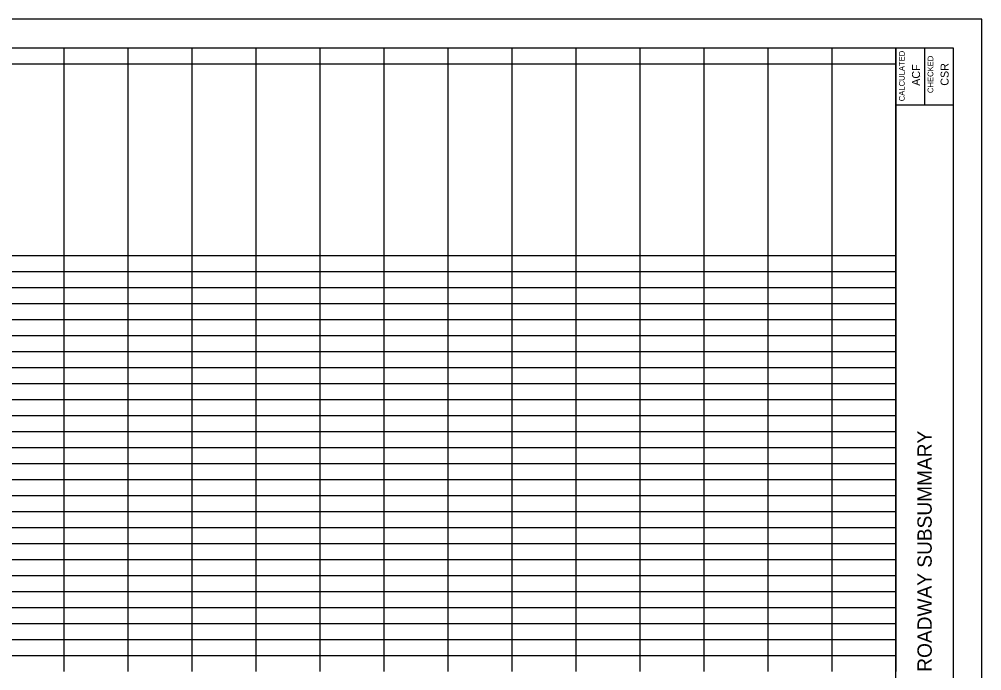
# Model space of a CAD drawing. Extents: x 0 to 34, y 0 to 22.
# Drawn here: x 17.17 to 34, y 10.6 to 22 of the extents above; entities that cross this region are included whole.
import ezdxf

# ---------------------------------------------------------------- set-up
doc = ezdxf.new("R2010")
doc.units = 0
for name, color, linetype in [('SH_Border', 7, 'Continuous'), ('SH_Cut_Line', 7, 'Continuous'), ('SH_Data', 7, 'Continuous')]:
    doc.layers.add(name, color=color, linetype=linetype)

msp = doc.modelspace()

# ---------------------------------------------------------------- linework, layer by layer
at = {"layer": 'SH_Border'}
for p, q in [((32.5, 0.5), (32.5, 21.5)), ((33, 21.5), (33, 20.5)), ((32.5, 20.5), (33.5, 20.5))]:
    msp.add_line(p, q, dxfattribs=at)
msp.add_lwpolyline([(2, 21.5), (33.5, 21.5), (33.5, 0.5), (2, 0.5)], close=True, dxfattribs=at)
at = {"layer": 'SH_Cut_Line'}
msp.add_lwpolyline([(0, 0), (34, 0), (34, 22), (0, 22)], close=True, dxfattribs=at)
at = {"layer": 'SH_Data'}
for p, q in [((15.706, 21.5), (17.945, 21.5)), ((17.945, 21.5), (21.304, 21.5)), ((17.945, 21.5), (17.945, 20.381)), ((19.065, 21.5), (19.065, 20.381)), ((20.184, 21.5), (20.184, 20.381)), ((21.304, 21.5), (22.423, 21.5)), ((21.304, 21.5), (21.304, 20.381)), ((22.423, 21.5), (28.022, 21.5)), ((22.423, 21.5), (22.423, 20.381)), ((23.543, 21.5), (23.543, 20.381)), ((24.663, 21.5), (24.663, 20.381)), ((25.782, 21.5), (25.782, 20.381)), ((26.902, 21.5), (26.902, 20.381)), ((28.022, 21.5), (32.5, 21.5)), ((28.022, 21.5), (28.022, 20.381)), ((29.141, 21.5), (29.141, 20.381)), ((30.261, 21.5), (30.261, 20.381)), ((31.38, 21.5), (31.38, 20.381)), ((32.5, 21.5), (32.5, 20.381)), ((15.706, 21.22), (17.945, 21.22)), ((17.945, 21.22), (21.304, 21.22)), ((21.304, 21.22), (22.423, 21.22)), ((22.423, 21.22), (28.022, 21.22)), ((28.022, 21.22), (32.5, 21.22)), ((32.92, 21.004), (32.92, 21.004)), ((33.42, 21.004), (33.42, 21.004)), ((17.945, 20.381), (17.945, 18.983)), ((19.065, 20.381), (19.065, 18.983)), ((20.184, 20.381), (20.184, 18.983)), ((21.304, 20.381), (21.304, 18.983)), ((22.423, 20.381), (22.423, 18.983)), ((23.543, 20.381), (23.543, 18.983)), ((24.663, 20.381), (24.663, 18.983)), ((25.782, 20.381), (25.782, 18.983)), ((26.902, 20.381), (26.902, 18.983)), ((28.022, 20.381), (28.022, 18.983)), ((29.141, 20.381), (29.141, 18.983)), ((30.261, 20.381), (30.261, 18.983)), ((31.38, 20.381), (31.38, 18.983)), ((32.5, 20.381), (32.5, 18.983)), ((17.945, 18.983), (17.945, 18.143)), ((19.065, 18.983), (19.065, 18.143)), ((20.184, 18.983), (20.184, 18.143)), ((21.304, 18.983), (21.304, 18.143)), ((22.423, 18.983), (22.423, 18.143)), ((23.543, 18.983), (23.543, 18.143)), ((24.663, 18.983), (24.663, 18.143)), ((25.782, 18.983), (25.782, 18.143)), ((26.902, 18.983), (26.902, 18.143)), ((28.022, 18.983), (28.022, 18.143)), ((29.141, 18.983), (29.141, 18.143)), ((30.261, 18.983), (30.261, 18.143)), ((31.38, 18.983), (31.38, 18.143)), ((32.5, 18.983), (32.5, 18.143)), ((17.945, 18.143), (17.945, 17.864)), ((19.065, 18.143), (19.065, 17.864)), ((20.184, 18.143), (20.184, 17.864)), ((21.304, 18.143), (21.304, 17.864)), ((22.423, 18.143), (22.423, 17.864)), ((23.543, 18.143), (23.543, 17.864)), ((24.663, 18.143), (24.663, 17.864)), ((25.782, 18.143), (25.782, 17.864)), ((26.902, 18.143), (26.902, 17.864)), ((28.022, 18.143), (28.022, 17.864)), ((29.141, 18.143), (29.141, 17.864)), ((30.261, 18.143), (30.261, 17.864)), ((31.38, 18.143), (31.38, 17.864)), ((32.5, 18.143), (32.5, 17.864)), ((15.706, 17.864), (17.945, 17.864)), ((17.945, 17.864), (21.304, 17.864)), ((17.945, 17.864), (17.945, 17.584)), ((19.065, 17.864), (19.065, 17.584)), ((20.184, 17.864), (20.184, 17.584)), ((21.304, 17.864), (22.423, 17.864)), ((21.304, 17.864), (21.304, 17.584)), ((22.423, 17.864), (28.022, 17.864)), ((22.423, 17.864), (22.423, 17.584)), ((23.543, 17.864), (23.543, 17.584)), ((24.663, 17.864), (24.663, 17.584)), ((25.782, 17.864), (25.782, 17.584)), ((26.902, 17.864), (26.902, 17.584)), ((28.022, 17.864), (32.5, 17.864)), ((28.022, 17.864), (28.022, 17.584)), ((29.141, 17.864), (29.141, 17.584)), ((30.261, 17.864), (30.261, 17.584)), ((31.38, 17.864), (31.38, 17.584)), ((32.5, 17.864), (32.5, 17.584)), ((15.706, 17.584), (17.945, 17.584)), ((17.945, 17.584), (21.304, 17.584)), ((17.945, 17.584), (17.945, 17.304)), ((19.065, 17.584), (19.065, 17.304)), ((20.184, 17.584), (20.184, 17.304)), ((21.304, 17.584), (22.423, 17.584)), ((21.304, 17.584), (21.304, 17.304)), ((22.423, 17.584), (28.022, 17.584)), ((22.423, 17.584), (22.423, 17.304)), ((23.543, 17.584), (23.543, 17.304)), ((24.663, 17.584), (24.663, 17.304)), ((25.782, 17.584), (25.782, 17.304)), ((26.902, 17.584), (26.902, 17.304)), ((28.022, 17.584), (32.5, 17.584)), ((28.022, 17.584), (28.022, 17.304)), ((29.141, 17.584), (29.141, 17.304)), ((30.261, 17.584), (30.261, 17.304)), ((31.38, 17.584), (31.38, 17.304)), ((32.5, 17.584), (32.5, 17.304)), ((15.706, 17.304), (17.945, 17.304)), ((17.945, 17.304), (21.304, 17.304)), ((17.945, 17.304), (17.945, 17.025)), ((19.065, 17.304), (19.065, 17.025)), ((20.184, 17.304), (20.184, 17.025)), ((21.304, 17.304), (22.423, 17.304)), ((21.304, 17.304), (21.304, 17.025)), ((22.423, 17.304), (28.022, 17.304)), ((22.423, 17.304), (22.423, 17.025)), ((23.543, 17.304), (23.543, 17.025)), ((24.663, 17.304), (24.663, 17.025)), ((25.782, 17.304), (25.782, 17.025)), ((26.902, 17.304), (26.902, 17.025)), ((28.022, 17.304), (32.5, 17.304)), ((28.022, 17.304), (28.022, 17.025)), ((29.141, 17.304), (29.141, 17.025)), ((30.261, 17.304), (30.261, 17.025)), ((31.38, 17.304), (31.38, 17.025)), ((32.5, 17.304), (32.5, 17.025)), ((15.706, 17.025), (17.945, 17.025)), ((17.945, 17.025), (21.304, 17.025)), ((17.945, 17.025), (17.945, 16.745)), ((19.065, 17.025), (19.065, 16.745)), ((20.184, 17.025), (20.184, 16.745)), ((21.304, 17.025), (22.423, 17.025)), ((21.304, 17.025), (21.304, 16.745)), ((22.423, 17.025), (28.022, 17.025)), ((22.423, 17.025), (22.423, 16.745)), ((23.543, 17.025), (23.543, 16.745)), ((24.663, 17.025), (24.663, 16.745)), ((25.782, 17.025), (25.782, 16.745)), ((26.902, 17.025), (26.902, 16.745)), ((28.022, 17.025), (32.5, 17.025)), ((28.022, 17.025), (28.022, 16.745)), ((29.141, 17.025), (29.141, 16.745)), ((30.261, 17.025), (30.261, 16.745)), ((31.38, 17.025), (31.38, 16.745)), ((32.5, 17.025), (32.5, 16.745)), ((15.706, 16.745), (17.945, 16.745)), ((17.945, 16.745), (21.304, 16.745)), ((17.945, 16.745), (17.945, 16.465)), ((19.065, 16.745), (19.065, 16.465)), ((20.184, 16.745), (20.184, 16.465)), ((21.304, 16.745), (22.423, 16.745)), ((21.304, 16.745), (21.304, 16.465)), ((22.423, 16.745), (28.022, 16.745)), ((22.423, 16.745), (22.423, 16.465)), ((23.543, 16.745), (23.543, 16.465)), ((24.663, 16.745), (24.663, 16.465)), ((25.782, 16.745), (25.782, 16.465)), ((26.902, 16.745), (26.902, 16.465)), ((28.022, 16.745), (32.5, 16.745)), ((28.022, 16.745), (28.022, 16.465)), ((29.141, 16.745), (29.141, 16.465)), ((30.261, 16.745), (30.261, 16.465)), ((31.38, 16.745), (31.38, 16.465)), ((32.5, 16.745), (32.5, 16.465)), ((15.706, 16.465), (17.945, 16.465)), ((17.945, 16.465), (21.304, 16.465)), ((17.945, 16.465), (17.945, 16.185)), ((19.065, 16.465), (19.065, 16.185)), ((20.184, 16.465), (20.184, 16.185)), ((21.304, 16.465), (22.423, 16.465)), ((21.304, 16.465), (21.304, 16.185)), ((22.423, 16.465), (28.022, 16.465)), ((22.423, 16.465), (22.423, 16.185)), ((23.543, 16.465), (23.543, 16.185)), ((24.663, 16.465), (24.663, 16.185)), ((25.782, 16.465), (25.782, 16.185)), ((26.902, 16.465), (26.902, 16.185)), ((28.022, 16.465), (32.5, 16.465)), ((28.022, 16.465), (28.022, 16.185)), ((29.141, 16.465), (29.141, 16.185)), ((30.261, 16.465), (30.261, 16.185)), ((31.38, 16.465), (31.38, 16.185)), ((32.5, 16.465), (32.5, 16.185)), ((15.706, 16.185), (17.945, 16.185)), ((17.945, 16.185), (21.304, 16.185)), ((17.945, 16.185), (17.945, 15.906)), ((19.065, 16.185), (19.065, 15.906)), ((20.184, 16.185), (20.184, 15.906)), ((21.304, 16.185), (22.423, 16.185)), ((21.304, 16.185), (21.304, 15.906)), ((22.423, 16.185), (28.022, 16.185)), ((22.423, 16.185), (22.423, 15.906)), ((23.543, 16.185), (23.543, 15.906)), ((24.663, 16.185), (24.663, 15.906)), ((25.782, 16.185), (25.782, 15.906)), ((26.902, 16.185), (26.902, 15.906)), ((28.022, 16.185), (32.5, 16.185)), ((28.022, 16.185), (28.022, 15.906)), ((29.141, 16.185), (29.141, 15.906)), ((30.261, 16.185), (30.261, 15.906)), ((31.38, 16.185), (31.38, 15.906)), ((32.5, 16.185), (32.5, 15.906)), ((15.706, 15.906), (17.945, 15.906)), ((17.945, 15.906), (21.304, 15.906)), ((17.945, 15.906), (17.945, 15.626)), ((19.065, 15.906), (19.065, 15.626)), ((20.184, 15.906), (20.184, 15.626)), ((21.304, 15.906), (22.423, 15.906)), ((21.304, 15.906), (21.304, 15.626)), ((22.423, 15.906), (28.022, 15.906)), ((22.423, 15.906), (22.423, 15.626)), ((23.543, 15.906), (23.543, 15.626)), ((24.663, 15.906), (24.663, 15.626)), ((25.782, 15.906), (25.782, 15.626)), ((26.902, 15.906), (26.902, 15.626)), ((28.022, 15.906), (32.5, 15.906)), ((28.022, 15.906), (28.022, 15.626)), ((29.141, 15.906), (29.141, 15.626)), ((30.261, 15.906), (30.261, 15.626)), ((31.38, 15.906), (31.38, 15.626)), ((32.5, 15.906), (32.5, 15.626)), ((15.706, 15.626), (17.945, 15.626)), ((17.945, 15.626), (21.304, 15.626)), ((17.945, 15.626), (17.945, 15.066)), ((19.065, 15.626), (19.065, 15.066)), ((20.184, 15.626), (20.184, 15.066)), ((21.304, 15.626), (22.423, 15.626)), ((21.304, 15.626), (21.304, 15.066)), ((22.423, 15.626), (28.022, 15.626)), ((22.423, 15.626), (22.423, 15.066)), ((23.543, 15.626), (23.543, 15.066)), ((24.663, 15.626), (24.663, 15.066)), ((25.782, 15.626), (25.782, 15.066)), ((26.902, 15.626), (26.902, 15.066)), ((28.022, 15.626), (32.5, 15.626)), ((28.022, 15.626), (28.022, 15.066)), ((29.141, 15.626), (29.141, 15.066)), ((30.261, 15.626), (30.261, 15.066)), ((31.38, 15.626), (31.38, 15.066)), ((32.5, 15.626), (32.5, 15.066)), ((15.706, 15.346), (17.945, 15.346)), ((17.945, 15.346), (21.304, 15.346)), ((21.304, 15.346), (22.423, 15.346)), ((22.423, 15.346), (28.022, 15.346)), ((28.022, 15.346), (32.5, 15.346)), ((15.706, 15.066), (17.945, 15.066)), ((17.945, 15.066), (21.304, 15.066)), ((17.945, 15.066), (17.945, 13.668)), ((19.065, 15.066), (19.065, 13.668)), ((20.184, 15.066), (20.184, 13.668)), ((21.304, 15.066), (22.423, 15.066)), ((21.304, 15.066), (21.304, 13.668)), ((22.423, 15.066), (28.022, 15.066)), ((22.423, 15.066), (22.423, 13.668)), ((23.543, 15.066), (23.543, 13.668)), ((24.663, 15.066), (24.663, 13.668)), ((25.782, 15.066), (25.782, 13.668)), ((26.902, 15.066), (26.902, 13.668)), ((28.022, 15.066), (32.5, 15.066)), ((28.022, 15.066), (28.022, 13.668)), ((29.141, 15.066), (29.141, 13.668)), ((30.261, 15.066), (30.261, 13.668)), ((31.38, 15.066), (31.38, 13.668)), ((32.5, 15.066), (32.5, 13.668)), ((15.706, 14.787), (17.945, 14.787)), ((17.945, 14.787), (21.304, 14.787)), ((21.304, 14.787), (22.423, 14.787)), ((22.423, 14.787), (28.022, 14.787)), ((28.022, 14.787), (32.5, 14.787)), ((15.706, 14.507), (17.945, 14.507)), ((17.945, 14.507), (21.304, 14.507)), ((21.304, 14.507), (22.423, 14.507)), ((22.423, 14.507), (28.022, 14.507)), ((28.022, 14.507), (32.5, 14.507)), ((15.706, 14.227), (17.945, 14.227)), ((17.945, 14.227), (21.304, 14.227)), ((21.304, 14.227), (22.423, 14.227)), ((22.423, 14.227), (28.022, 14.227)), ((28.022, 14.227), (32.5, 14.227)), ((15.706, 13.948), (17.945, 13.948)), ((17.945, 13.948), (21.304, 13.948)), ((21.304, 13.948), (22.423, 13.948)), ((22.423, 13.948), (28.022, 13.948)), ((28.022, 13.948), (32.5, 13.948)), ((15.706, 13.668), (17.945, 13.668)), ((17.945, 13.668), (21.304, 13.668)), ((17.945, 13.668), (17.945, 11.99)), ((19.065, 13.668), (19.065, 11.99)), ((20.184, 13.668), (20.184, 11.99)), ((21.304, 13.668), (22.423, 13.668)), ((21.304, 13.668), (21.304, 11.99)), ((22.423, 13.668), (28.022, 13.668)), ((22.423, 13.668), (22.423, 11.99)), ((23.543, 13.668), (23.543, 11.99)), ((24.663, 13.668), (24.663, 11.99)), ((25.782, 13.668), (25.782, 11.99)), ((26.902, 13.668), (26.902, 11.99)), ((28.022, 13.668), (32.5, 13.668)), ((28.022, 13.668), (28.022, 11.99)), ((29.141, 13.668), (29.141, 11.99)), ((30.261, 13.668), (30.261, 11.99)), ((31.38, 13.668), (31.38, 11.99)), ((32.5, 13.668), (32.5, 11.99)), ((15.706, 13.388), (17.945, 13.388)), ((17.945, 13.388), (21.304, 13.388)), ((21.304, 13.388), (22.423, 13.388)), ((22.423, 13.388), (28.022, 13.388)), ((28.022, 13.388), (32.5, 13.388)), ((33, 13.292), (33, 13.292)), ((15.706, 13.108), (17.945, 13.108)), ((17.945, 13.108), (21.304, 13.108)), ((21.304, 13.108), (22.423, 13.108)), ((22.423, 13.108), (28.022, 13.108)), ((28.022, 13.108), (32.5, 13.108)), ((15.706, 12.829), (17.945, 12.829)), ((17.945, 12.829), (21.304, 12.829)), ((21.304, 12.829), (22.423, 12.829)), ((22.423, 12.829), (28.022, 12.829)), ((28.022, 12.829), (32.5, 12.829)), ((15.706, 12.549), (17.945, 12.549)), ((17.945, 12.549), (21.304, 12.549)), ((21.304, 12.549), (22.423, 12.549)), ((22.423, 12.549), (28.022, 12.549)), ((28.022, 12.549), (32.5, 12.549)), ((15.706, 12.269), (17.945, 12.269)), ((17.945, 12.269), (21.304, 12.269)), ((21.304, 12.269), (22.423, 12.269)), ((22.423, 12.269), (28.022, 12.269)), ((28.022, 12.269), (32.5, 12.269)), ((15.706, 11.99), (17.945, 11.99)), ((17.945, 11.99), (21.304, 11.99)), ((17.945, 11.99), (17.945, 10.591)), ((19.065, 11.99), (19.065, 10.591)), ((20.184, 11.99), (20.184, 10.591)), ((21.304, 11.99), (22.423, 11.99)), ((21.304, 11.99), (21.304, 10.591)), ((22.423, 11.99), (28.022, 11.99)), ((22.423, 11.99), (22.423, 10.591)), ((23.543, 11.99), (23.543, 10.591)), ((24.663, 11.99), (24.663, 10.591)), ((25.782, 11.99), (25.782, 10.591)), ((26.902, 11.99), (26.902, 10.591)), ((28.022, 11.99), (32.5, 11.99)), ((28.022, 11.99), (28.022, 10.591)), ((29.141, 11.99), (29.141, 10.591)), ((30.261, 11.99), (30.261, 10.591)), ((31.38, 11.99), (31.38, 10.591)), ((32.5, 11.99), (32.5, 10.591)), ((15.706, 11.71), (17.945, 11.71)), ((17.945, 11.71), (21.304, 11.71)), ((21.304, 11.71), (22.423, 11.71)), ((22.423, 11.71), (28.022, 11.71)), ((28.022, 11.71), (32.5, 11.71)), ((15.706, 11.43), (17.945, 11.43)), ((17.945, 11.43), (21.304, 11.43)), ((21.304, 11.43), (22.423, 11.43)), ((22.423, 11.43), (28.022, 11.43)), ((28.022, 11.43), (32.5, 11.43)), ((15.706, 11.15), (17.945, 11.15)), ((17.945, 11.15), (21.304, 11.15)), ((21.304, 11.15), (22.423, 11.15)), ((22.423, 11.15), (28.022, 11.15)), ((28.022, 11.15), (32.5, 11.15)), ((15.706, 10.871), (17.945, 10.871)), ((17.945, 10.871), (21.304, 10.871)), ((21.304, 10.871), (22.423, 10.871)), ((22.423, 10.871), (28.022, 10.871)), ((28.022, 10.871), (32.5, 10.871))]:
    msp.add_line(p, q, dxfattribs=at)

# ---------------------------------------------------------------- texts
for s, height, p in [('CALCULATED', 0.1, (32.652, 20.565)), ('CHECKED', 0.1, (33.152, 20.708)), ('CSR', 0.14, (33.42, 20.837)), ('ACF', 0.14, (32.92, 20.836)), ('ROADWAY SUBSUMMARY', 0.25, (33.125, 10.584))]:
    msp.add_text(s, height=height, rotation=90, dxfattribs=at).set_placement(p)

doc.saveas('drawing.dxf')
